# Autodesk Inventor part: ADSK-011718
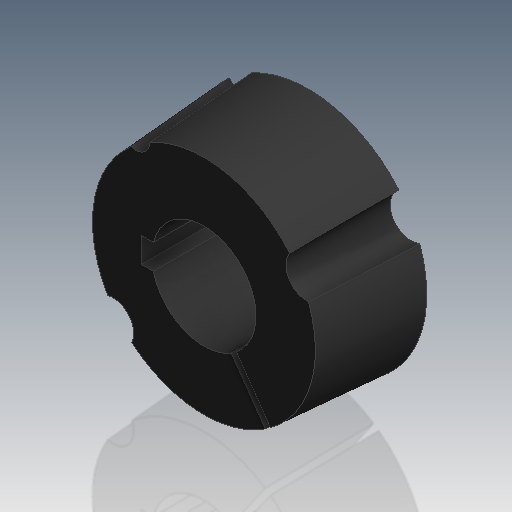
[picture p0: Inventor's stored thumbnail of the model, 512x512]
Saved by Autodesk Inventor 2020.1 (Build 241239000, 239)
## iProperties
Created: 1999-11
Part Number: ADSK-011718
Description: BUSHING,T/L,1.000B,2.250
Document SubType Name: Modeling
Designer: dmcquary
Material: Acier doux
Density: 7.86 g/cm^3
Appearance: Rubber-Black
Mass: 353.614 g
Surface Area: 109.586 cm^2
Volume: 44.9891 cm^3
Control State: 0
Checked Out: False
Last Check In By: tgregory
Master: False
Shininess: 60.0
Length Units: 11269
Angle Units: 11279
Time Units: 11290
Mass Units: 11283
Length Display Precision: 3
Angle Display Precision: 2
Compacted: True
Dimensions: 57x25x57 mm
Mass: 0,354 kg
VLT_Material: Acier doux
DocNumber: ADSK-011718.ipt
Folder: 01 - Themengebiete\Simplification\01 - Packaging machine\
VDS_Category: 3D Komponenten
Density: 0.0
Volumn: 0.0
Area: 0.0
PropertySet Name: Model Information
Author: dmcquary
Revision Number: -
Title: BUSHING,T/L,1.000B,2.250
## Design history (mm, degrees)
node "Solide1"
  node "Extrusion1" dims "d1" = 25, "d2" = -4 deg
  node "Extrusion2" dims "d8" = 25.4, "d9" = 0
  node "Hole1" dims "d15" = 10, "d16" = 9.525, "d17" = 6.35, "d18" = 60 deg, "d19" = 25.4, "d20" = 118 deg, "d34" = 6
  node "Hole2" dims "d23" = 6.6, "d24" = 9.525, "d25" = 6.35, "d26" = 60 deg, "d27" = 22.2, "d28" = 118 deg, "d35" = 16
  node "Extrusion3" dims "d32" = 25.4, "d33" = 0
workplane "Work Plane1"
sketch "Sketch3"
  geometry: L1 (-15, 3)-(-12.135, 3) reference; L2 (0, 0)-(-28.5, 0); L3 (0, 0)-(-21.832, -18.319); L4 (0, 0)-(24.682, 14.25); C1 r 26.752 at (0, 0) reference; A1 r 28.5 centre (0, 0) between (-28.5, 0) and (-21.832, -18.319); 2 further points
  constraints: 6 end point, 3 coincident, 3 point on circle, 1 centre point, 1 parallel
  dimensions: "d10" = 57 diameter of A1; "d12" = 40 deg angle of L3 L2; "d14" = 170 deg angle of L4 L3
sketch "Sketch4"
  geometry: L1 (-15, 3)-(-12.135, 3) reference; L2 (0, 0)-(-16.347, 23.346); L3 (0, 0)-(-28.935, 0); A1 r 12.5 centre (0, 0) between (-12.135, -3) and (-12.135, 3) reference; 1 further point
  constraints: 4 end point, 1 coincident, 1 parallel
  dimensions: "d21" = 28.5 distance of L2.start L2.end; "d22" = 55 deg angle of L3 L2
workaxis "Work Axis1"
node "Corps solides"
node "Corps surfaciques"
sketch "Sketch1"
  geometry: C1 r 28.5 at (0, 0)
  constraints: 1 centre point
  dimensions: "d0" = 57 diameter of C1
sketch "Sketch2"
  geometry: L1 (0, 0)-(18.01, 0); L2 (9, 3)-(15, 3); L3 (15, 3)-(15, -3); L4 (15, -3)-(9, -3); L5 (9, -3)-(9, 3); C1 r 28.5 at (0, 0) reference; C2 r 12.5 at (0, 0)
  constraints: 10 end point, 2 coincident, 2 horizontal, 2 parallel, 2 perpendicular, 1 centre point
  dimensions: "d3" = 25 diameter of C2; "d4" = 6 distance of L3.end L4.end; "d6" = 3 distance from line of C1.centre L2; "d7" = 15 distance from line of L3 C2.centre
sketch "Sketch6"
  geometry: L1 (-6.522, -8.007)-(-5.294, -8.868); L2 (-5.294, -8.868)-(-17.217, -25.896); L3 (-17.217, -25.896)-(-18.446, -25.035); L4 (-18.446, -25.035)-(-6.522, -8.007); L5 (16.347, 23.346)-(0, 0); A1 r 12.5 centre (0, 0) between (12.135, 3) and (12.135, -3) reference; A2 r 3.3 centre (16.347, 23.346) between (13.539, 25.079) and (18.936, 21.3) reference; A3 r 28.5 centre (0, 0) between (24.698, -14.222) and (18.936, 21.3) reference
  constraints: 10 end point, 2 parallel, 1 perpendicular
  dimensions: "d29" = 1.5 distance of L2.end L3.end; "d30" = 0.75 distance from line of L4 A1.centre (= 0.5 x d29); "d31" = 180 deg angle of L2 L5
